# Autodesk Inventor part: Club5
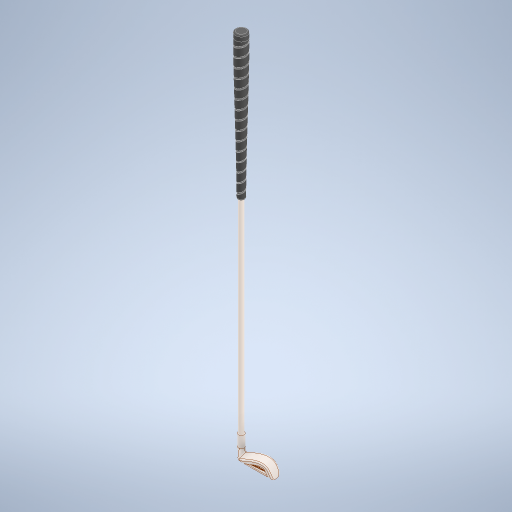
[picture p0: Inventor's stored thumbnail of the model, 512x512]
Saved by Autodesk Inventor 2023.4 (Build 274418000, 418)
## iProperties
Created: 2009-07
Part Number: Club5
Material: Générique
Document SubType Name: Modeling
Designer: bruno
Density: 1 g/cm^3
Appearance: Par défaut
Mass: 218.758 g
Surface Area: 590.453 cm^2
Volume: 218.758 cm^3
Sending System: SolidWorks 2013
Last Author: PAVEL
Last Saved: 2013-05-30
Author: bruno
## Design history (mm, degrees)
node "golf club.SLDPRT"
node "Solide1"
feature "Shaft"
node "Solide2"
feature "Grip"
node "Solide3"
feature "Clubhead"
